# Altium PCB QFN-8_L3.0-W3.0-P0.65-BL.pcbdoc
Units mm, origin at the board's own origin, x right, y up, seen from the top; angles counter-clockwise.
Board outline 16.1 x 16.97 mm, 2 copper layers (Top Layer, Bottom Layer), stack 0 mm thick; 1 components, 0 nets, 8 pads, 0 vias.
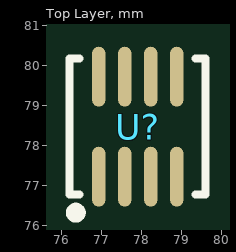
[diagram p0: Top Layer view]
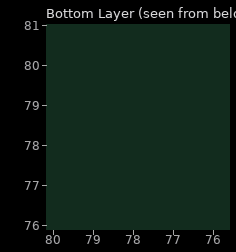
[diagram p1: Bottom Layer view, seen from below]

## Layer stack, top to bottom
Top Layer: signal copper (thickness not stored)
Bottom Layer: signal copper (thickness not stored)

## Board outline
85.95,69.85 69.85,69.85 69.85,86.824 85.95,86.824

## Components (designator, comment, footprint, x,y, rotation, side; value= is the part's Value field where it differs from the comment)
U? "" QFN-8_L3.0-W3.0-P0.65-BL 77.9,78.474 r0 top

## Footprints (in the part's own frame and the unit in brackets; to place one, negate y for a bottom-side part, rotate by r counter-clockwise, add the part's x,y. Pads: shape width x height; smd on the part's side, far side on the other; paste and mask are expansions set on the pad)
QFN-8_L3.0-W3.0-P0.65-BL [mm]
  oval 0.33x1.5 smd: 1(-0.975,-1.25) 2(-0.325,-1.25) 3(0.325,-1.25) 4(0.975,-1.25) 5(0.975,1.25) 6(0.325,1.25) 7(-0.325,1.25) 8(-0.975,1.25)
  silkscreen extent -1.7,-2.27 1.7,1.7

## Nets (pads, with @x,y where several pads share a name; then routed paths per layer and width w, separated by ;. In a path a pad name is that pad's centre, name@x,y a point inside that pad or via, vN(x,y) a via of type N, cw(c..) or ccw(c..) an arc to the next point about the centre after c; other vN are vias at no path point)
pads on no net: U?.1 U?.2 U?.3 U?.4 U?.5 U?.6 U?.7 U?.8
